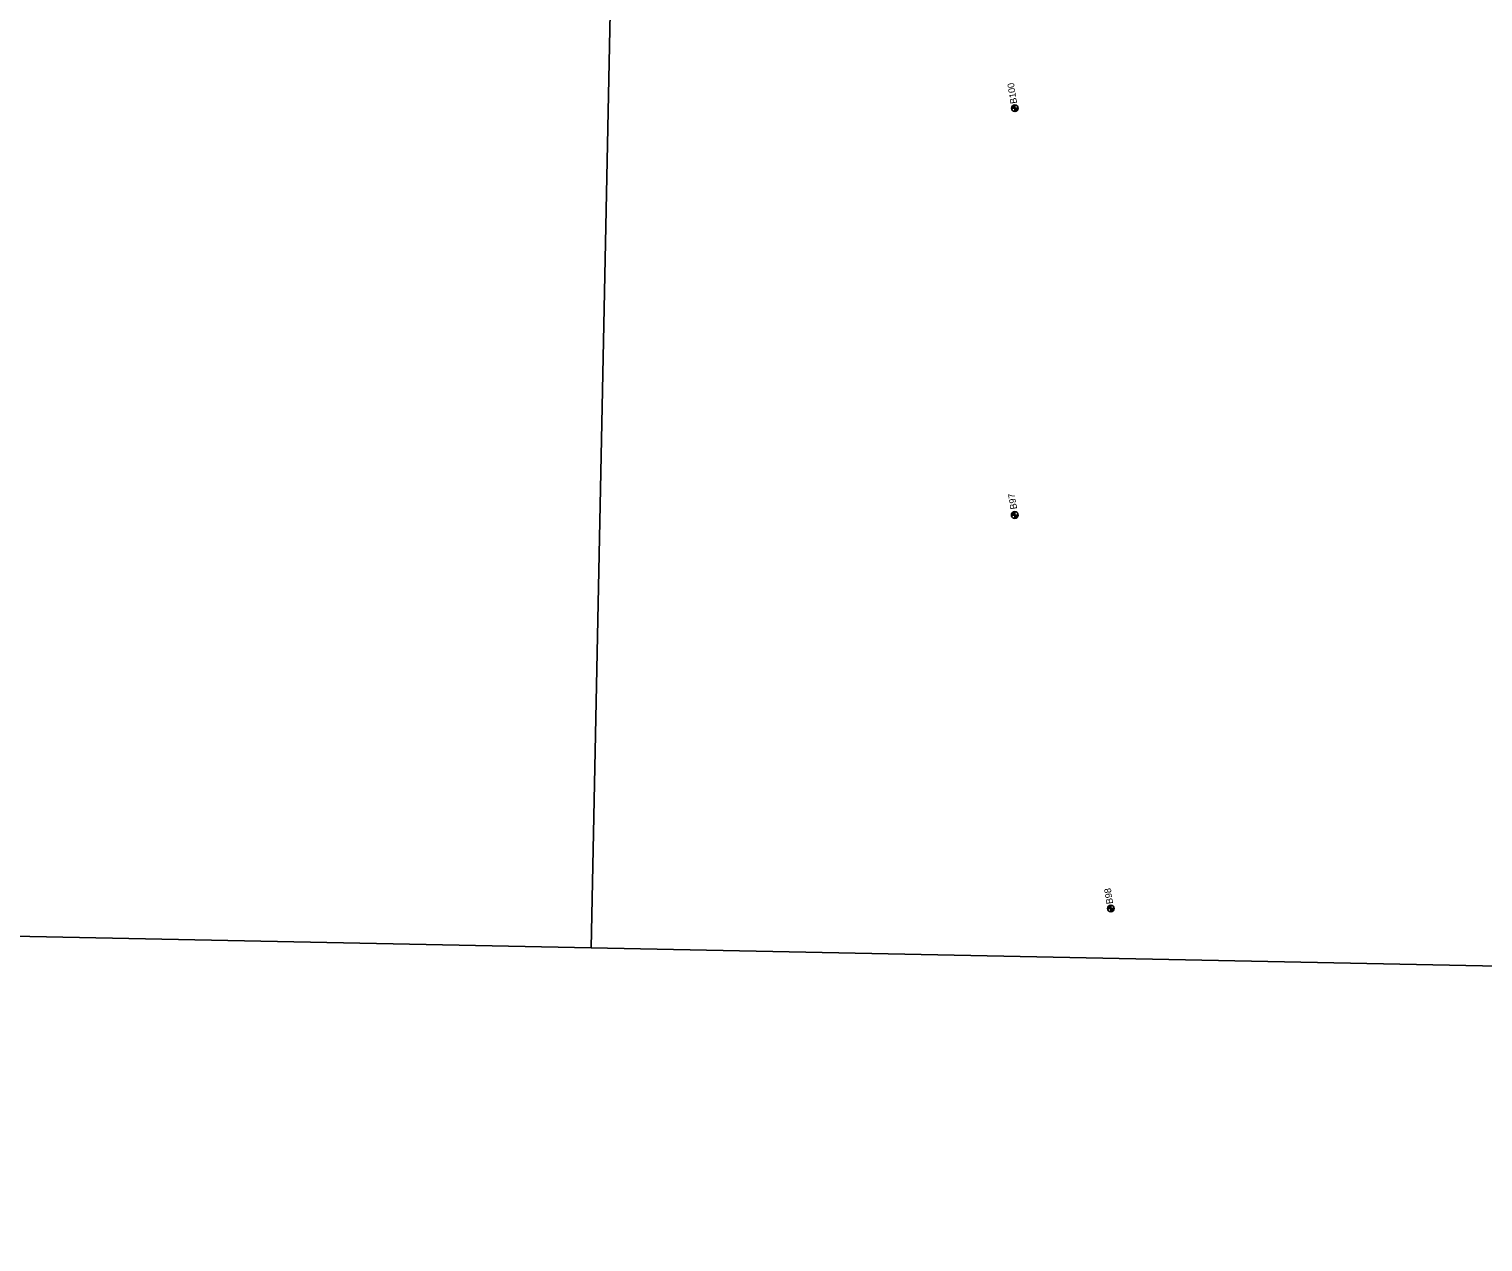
# Model space of a CAD drawing. Extents: x 345549 to 379569, y 127949 to 230467.
# Drawn here: x 354537 to 356698, y 180740 to 182543 of the extents above; entities that cross this region are included whole.
import ezdxf

# ---------------------------------------------------------------- set-up
doc = ezdxf.new("R2010")
doc.units = 0
for name, color, linetype in [('E_RDWY', 7, 'Continuous'), ('E_SOIL_BORE1 [KAPUR_CADDS_LEVELS]', 7, 'Continuous'), ('E_SOIL_BORE2 [KAPUR_CADDS_LEVELS]', 7, 'Continuous'), ('P_MARK', 7, 'Continuous'), ('PLT_Sheet_Info', 7, 'Continuous')]:
    doc.layers.add(name, color=color, linetype=linetype)

msp = doc.modelspace()

# ---------------------------------------------------------------- linework, layer by layer
at = {"layer": 'E_RDWY'}
msp.add_line((355372.5, 181177.5), (356094.5, 217027.6), dxfattribs=at)
at = {"layer": 'P_MARK'}
for p, q in [((355997.3, 182425.8), (356007.3, 182425.8)), ((356002.3, 182430.8), (356002.3, 182420.8)), ((355997.1, 181821), (356007.1, 181821)), ((356002.1, 181826), (356002.1, 181816)), ((356140, 181236), (356150, 181236)), ((356145, 181241), (356145, 181231))]:
    msp.add_line(p, q, dxfattribs=at)
for centre in [(356002.3, 182425.8), (356002.1, 181821), (356145, 181236)]:
    msp.add_circle(centre, 5, dxfattribs=at)
for centre, radius, start, end in [((356002.3, 182425.8), 4.5, 89.9869, 179.9869), ((356002.3, 182425.8), 4, 89.9869, 179.9869), ((356002.3, 182425.8), 3.5, 89.9869, 179.9869), ((356002.3, 182425.8), 3, 89.9869, 179.9869), ((356002.3, 182425.8), 2.5, 89.9869, 179.9869), ((356002.3, 182425.8), 2, 89.9869, 179.9869), ((356002.3, 182425.8), 1.5, 89.9869, 179.9869), ((356002.3, 182425.8), 1, 89.9869, 179.9869), ((356002.3, 182425.8), 0.5, 89.9869, 179.9869), ((356002.3, 182425.8), 4.5, 269.9869, 359.9869), ((356002.3, 182425.8), 4, 269.9869, 359.9869), ((356002.3, 182425.8), 3.5, 269.9869, 359.9869), ((356002.3, 182425.8), 3, 269.9869, 359.9869), ((356002.3, 182425.8), 2.5, 269.9869, 359.9869), ((356002.3, 182425.8), 2, 269.9869, 359.9869), ((356002.3, 182425.8), 1.5, 269.9869, 359.9869), ((356002.3, 182425.8), 1, 269.9869, 359.9869), ((356002.3, 182425.8), 0.5, 269.9869, 359.9869), ((356002.1, 181821), 4.5, 89.9869, 179.9869), ((356002.1, 181821), 4, 89.9869, 179.9869), ((356002.1, 181821), 3.5, 89.9869, 179.9869), ((356002.1, 181821), 3, 89.9869, 179.9869), ((356002.1, 181821), 2.5, 89.9869, 179.9869), ((356002.1, 181821), 2, 89.9869, 179.9869), ((356002.1, 181821), 1.5, 89.9869, 179.9869), ((356002.1, 181821), 1, 89.9869, 179.9869), ((356002.1, 181821), 0.5, 89.9869, 179.9869), ((356002.1, 181821), 4.5, 269.9869, 359.9869), ((356002.1, 181821), 4, 269.9869, 359.9869), ((356002.1, 181821), 3.5, 269.9869, 359.9869), ((356002.1, 181821), 3, 269.9869, 359.9869), ((356002.1, 181821), 2.5, 269.9869, 359.9869), ((356002.1, 181821), 2, 269.9869, 359.9869), ((356002.1, 181821), 1.5, 269.9869, 359.9869), ((356002.1, 181821), 1, 269.9869, 359.9869), ((356002.1, 181821), 0.5, 269.9869, 359.9869), ((356145, 181236), 4.5, 89.9869, 179.9869), ((356145, 181236), 4, 89.9869, 179.9869), ((356145, 181236), 3.5, 89.9869, 179.9869), ((356145, 181236), 3, 89.9869, 179.9869), ((356145, 181236), 2.5, 89.9869, 179.9869), ((356145, 181236), 2, 89.9869, 179.9869), ((356145, 181236), 1.5, 89.9869, 179.9869), ((356145, 181236), 1, 89.9869, 179.9869), ((356145, 181236), 0.5, 89.9869, 179.9869), ((356145, 181236), 4.5, 269.9869, 359.9869), ((356145, 181236), 4, 269.9869, 359.9869), ((356145, 181236), 3.5, 269.9869, 359.9869), ((356145, 181236), 3, 269.9869, 359.9869), ((356145, 181236), 2.5, 269.9869, 359.9869), ((356145, 181236), 2, 269.9869, 359.9869), ((356145, 181236), 1.5, 269.9869, 359.9869), ((356145, 181236), 1, 269.9869, 359.9869), ((356145, 181236), 0.5, 269.9869, 359.9869)]:
    msp.add_arc(centre, radius, start, end, dxfattribs=at)
at = {"layer": 'PLT_Sheet_Info'}
msp.add_line((377080.8, 180740.3), (347086.9, 181344.4), dxfattribs=at)

# ---------------------------------------------------------------- texts
at = {"layer": 'E_SOIL_BORE1 [KAPUR_CADDS_LEVELS]'}
for s, p in [('B97', (356005.7, 181830.2)), ('B98', (356148.5, 181243.4))]:
    msp.add_text(s, height=10, rotation=98.957, dxfattribs=at).set_placement(p)
at = {"layer": 'E_SOIL_BORE2 [KAPUR_CADDS_LEVELS]'}
msp.add_text('B100', height=10, rotation=98.957, dxfattribs=at).set_placement((356005.7, 182433.2))

doc.saveas('drawing.dxf')
